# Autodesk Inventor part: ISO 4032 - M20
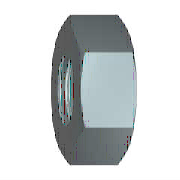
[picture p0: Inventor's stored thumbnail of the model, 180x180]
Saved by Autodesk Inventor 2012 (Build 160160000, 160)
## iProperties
Comments: To add or edit properties for Autodesk Inventor files, use iProperties.
Company: CAD-Verlag
Shininess: 64.0
Length Units: 11269
Angle Units: 11279
Time Units: 11290
Mass Units: 11283
Length Display Precision: 3
Angle Display Precision: 2
Compacted: True
Alert: To add or edit properties for Autodesk Inventor files, use iProperties.
Created: 2004-09
Part Number: ISO 4032 - M20
Vendor: Autodesk Inc.
Document SubType Name: Modeling
Designer: Greiling
Material: Standard
Description: Sechskantmutter
Standard: ISO 4032
Size Designation: M20
Density: 1 g/cm^3
Density: 0.0
Volumn: 0.0
Area: 0.0
PropertySet Name: Model Information
Control State: 0
Master: False
Checked Out: False
EGR: 1
Author: Jürgen Kronas
Revision Number: 8
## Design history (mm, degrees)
sketch "Skizze1"
  geometry: L1 (-17.321, 0)-(-8.66, 15); L2 (-8.66, 15)-(8.66, 15); L3 (8.66, 15)-(17.321, 0); L4 (17.321, 0)-(8.66, -15); L5 (8.66, -15)-(-8.66, -15); L6 (-8.66, -15)-(-17.321, 0); 2 further points
  constraints: 12 end point, 1 coincident, 1 horizontal, 11 other
  dimensions: "d0" = 34.64102 distance of L3.end L1.start (= 1.1547 x SW)
extrude "Körper" new body sketch "Skizze1" distance "d1" = 18 (= KOH); taper "d2" = 0 deg
revolve "Fase1" stored, may be unused: angle "d7" = 90 deg
sketch "Skizze3"
  geometry: A1 r 15 centre (0, 0) between (-7.5, -12.99) and (7.5, -12.99) reference; 1 further point
  constraints: 1 coincident
hole "Gewinde" sketch "Skizze3" diameter "d25" = 17.294; stored, may be unused: countersink angle "d29" = 82 deg, drill point angle "d31" = 118 deg; dims "d26" = 6, "d27" = 4, "d28" = 2, "d30" = 8
node "Volumenkörper1"
node "Volumenkörpern"
node "Oberflächenkörpern"
chamfer "Fase2" distance "d8" = 1.35316 (= -0.5 x GD1 + 0.5 x NND); stored, may be unused: angle "d9" = 30 deg, second distance "d40" = 1.35316 (= -0.5 x GD1 + 0.5 x NND)
chamfer "Fase3" distance "d10" = 1.35316 (= -0.5 x GD1 + 0.5 x NND); stored, may be unused: angle "d11" = 30 deg, second distance "d41" = 1.35316 (= -0.5 x GD1 + 0.5 x NND)
sketch "Skizze2"
  geometry: L1 (0, 8.66)-(0, 17.321) reference; L2 (0, 17.321)-(18, 17.321) reference; L3 (18, 8.66)-(18, 17.321) reference; L4 (-1.8, 0)-(23.4, 0) reference; L5 (1.34, 17.321)-(0, 15); L6 (16.66, 17.321)-(18, 15)
  constraints: 4 end point, 4 point on line
  dimensions: "d3" = 30 deg angle of L1 L5 (= ANG1); "d4" = 30 deg angle of L3 L6 (= ANG2); "d5" = 30 diameter of L5.end L4 (= SW0); "d6" = 30 diameter of L6.end L4 (= SW01)
other parameters: "ANG1" = 30 deg [user parameter; used in 1 equation term], "ANG2" = 30 deg [user parameter; used in 1 equation term], "KOH" = 18 [user parameter; used in 1 equation term], "SW0" = 30 [user parameter; used in 2 equation terms], "SW01" = 30 (= SW0) [user parameter; used in 1 equation term], "GD1" = 17.29367 (computed from THREADDIA, TPU, TOA) [user parameter; used in 4 equation terms], "d13" = 0, "d14" = 0, "d39" = 0, "E0" = 34.65 (= 1.155 x SW) [user parameter], "TPU" = 2.5 [user parameter; used in 4 equation terms], "GUL" = 1.35317 (= 0.541266 x TPU) [user parameter], "GAL" = 1.35317 (= 0.541266 x TPU) [user parameter], "PTC" = 2.5 (= TPU) [user parameter], "TOA" = 30 deg [user parameter; used in 1 equation term]
